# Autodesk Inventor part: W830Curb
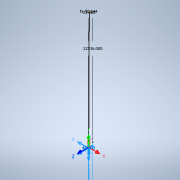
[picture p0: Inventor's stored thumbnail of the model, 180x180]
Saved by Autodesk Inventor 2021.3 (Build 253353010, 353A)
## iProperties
Created: 2021-10
Part Number: W830Curb
Material: Concrete, Cast-in-Place, Gray
Document SubType Name: Modeling
Designer: u1426
Density: 2.40731 g/cm^3
Appearance: Flat - Gray 1
Author: u1426
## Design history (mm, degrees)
node "Annotations"
  node "Linear Dimension 1" dims "d10" = 1016, "d43" = 0, "d132" = 279.4, "d133" = 279.4, "d163" = 572414.4, "d165" = 31014.11722 (derived), "d195" = 2289.6576 (derived)
  node "Linear Dimension 2" dims "d10" = 1016, "d43" = 0, "d132" = 279.4, "d133" = 279.4, "d163" = 572414.4, "d170" = 2819.23425 (derived), "d195" = 2289.6576 (derived)
sketch "Sketch2"
  geometry: L1 (0, -1016)-(-279.4, -1016); L2 (572414.4, -3305.658)-(572693.8, -3305.658); L3 (0, -1016)-(572414.4, -3305.658); 1 further point
  constraints: 6 end point, 2 horizontal
  dimensions: "d10" = 1016 distance of point (0, 0) L1.start; "d43" = 0 horizontal distance of L1.start point (0, 0); "d132" = 279.4 distance of L1.start L1.end; "d133" = 279.4 distance of L2.start L2.end; "d163" = 572414.4 horizontal distance of L2.start L1.start; "d195" = 2289.6576 vertical distance of L1.start L2.start (derived)
workpoint "Work Point1"
pattern_linear "Rectangular Pattern1" dims "d158" = 2133.6
workpoint "Work Point14"
pattern_linear "Rectangular Pattern2" dims "d162" = 2133.6
workpoint "Work Point16"
  workplane "Work Plane1"
sketch "Sketch8"
  geometry: L1 (0, -1038.244)-(-978.62, -1038.244); L2 (-978.62, -1038.244)-(-978.62, -877.156); L3 (-978.62, -877.156)-(0, -877.156); L4 (0, -877.156)-(0, -1038.244); 1 further point
  constraints: 8 end point, 2 parallel, 1 horizontal, 1 perpendicular
extrude "Extrusion5" new body sketch "Sketch8" distance "d193" = 25.4; taper "d194" = 0 deg
feature "Sketch Driven Pattern1"
body "Solid6"
workpoint "Work Point2"
workpoint "Work Point15"
workpoint "Work Point44"
workpoint "Work Point45"
workpoint "Work Point46"
workpoint "Work Point47"
workpoint "Work Point48"
workpoint "Work Point49"
workpoint "Work Point50"
workpoint "Work Point51"
workpoint "Work Point52"
other parameters: "d59" = 12.7, "d63" = 12.7, "d166" = 1612.392, "d172" = 0, "d173" = 0, "d174" = 0, "d175" = 0.1309, "d176" = 0, "d177" = 0
